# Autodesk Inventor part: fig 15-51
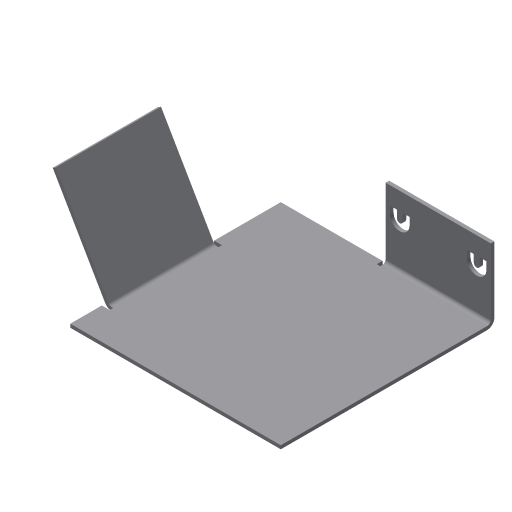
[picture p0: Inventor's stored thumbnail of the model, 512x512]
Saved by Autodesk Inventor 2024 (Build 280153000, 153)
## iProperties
Shininess: 77.0
Angle Display Precision: 2
Document Length Units: 11269
Document Angle Units: 11279
Document Time Units: 11290
Document Mass Units: 11283
Document Length Units Precision: 3
Document Angle Units Precision: 2
Created: 2002-04
Part Number: fig 15-51
Document SubType Name: Sheet Metal
Density: 1 g/cm^3
Sheet Metal Rule: Default
Material: Generic
Appearance: Default
Density: 0.0
Volumn: 0.0
Area: 0.0
PropertySet Name: Model Information
Control State: 0
Master: False
Checked Out: False
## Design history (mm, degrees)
node "Face1"
  sketch "Sketch1"
    geometry: L1 (12.647, 25.882)-(12.647, -14.118); L2 (12.647, -14.118)-(-17.353, -14.118); L3 (-17.353, -14.118)-(-17.353, 15.882); L4 (-17.353, 15.882)-(-2.353, 15.882); L5 (-2.353, 15.882)-(-2.353, 25.882); L6 (-2.353, 25.882)-(12.647, 25.882); 1 further point
    constraints: 12 end point, 4 parallel, 1 perpendicular
    dimensions: "d5" = 30 distance of L2.end L3.end; "d6" = 10 distance of L4.end L5.end; "d7" = 15 distance of L3.end L4.end; "d25" = 15 distance of L5.end L1.start
sketch "Sketch3"
  geometry: L1 (10, -15)-(10, 0)
  constraints: 2 end point
feature "Fold3" sketch "Sketch3" dims "d26" = 0.5 (= BendRadius), "d27" = 90 deg, "d28" = 0.5 (= BendRadius), "d96" = 0.5 (= BendReliefWidth), "d97" = 0.25 (= BendReliefDepth), "d98" = 1 (= MinimumRemnant), "d107" = 0.5 (= Thickness), "SeamGap" = 0.01
node "Flange2"
sketch "Sketch6"
  geometry: L1 (-6.914, 3.413)-(-5.843, 3.413); L2 (-5.843, 0.624)-(-6.914, 0.624); L3 (-6.914, 2.432)-(-5.843, 2.432); L4 (-5.843, 1.605)-(-6.914, 1.605); L5 (-6.914, 0.624)-(-6.914, 1.605); L6 (-6.914, 2.432)-(-6.914, 3.413); L7 (-6.914, 12.568)-(-6.914, 11.587); L8 (-6.914, 14.376)-(-6.914, 13.395); L9 (-6.914, 11.587)-(-5.843, 11.587); L10 (-5.843, 14.376)-(-6.914, 14.376); L11 (-6.914, 12.568)-(-5.843, 12.568); L12 (-5.843, 13.395)-(-6.914, 13.395); A1 r 1.394 centre (-5.843, 2.018) between (-5.843, 0.624) and (-5.843, 3.413); A2 r 0.413 centre (-5.843, 2.018) between (-5.843, 1.605) and (-5.843, 2.432); A3 r 1.394 centre (-5.843, 12.982) between (-5.843, 11.587) and (-5.843, 14.376); A4 r 0.413 centre (-5.843, 12.982) between (-5.843, 12.568) and (-5.843, 13.395)
  constraints: 24 end point, 8 point on circle, 4 centre point, 3 equal length, 1 perpendicular
cut "Cut1" sketch "Sketch6" dims "d49" = 0.5 (= Thickness), "d50" = 0
body "Solid1"
face "Plate1" dims "d107" = 0.5 (= Thickness)
sketch "Sketch5"
  geometry: L1 (20, 0)-(5, 0); L2 (5, 0)-(5, 15); L3 (5, 15)-(20, 15); L4 (20, 15)-(20, 0)
  constraints: 8 end point
face "Plate6" dims "d35" = 10, "d36" = 5, "d38" = 15, "d39" = 60 deg, "d40" = 0.5 (= BendRadius), "d107" = 0.5 (= Thickness), "MinimumRemnant" = 1 (= 2 x Thickness), "BendReliefWidth" = 0.5 (= Thickness)
bend "Bend5" dims "d38" = 15, "d39" = 60 deg, "d40" = 0.5 (= BendRadius), "d99" = 0.5 (= BendReliefWidth), "d100" = 0.25 (= BendReliefDepth), "d101" = 1 (= MinimumRemnant), "d107" = 0.5 (= Thickness), "SeamGap" = 0.01, "MinimumRemnant" = 1 (= 2 x Thickness), "BendReliefWidth" = 0.5 (= Thickness), "TransitionRadius" = 0.5 (= BendRadius)
other parameters: "Thickness" = 0.5, "BendRadius" = 0.5 (= Thickness), "BendReliefDepth" = 0.25 (= 0.5 x Thickness), "CornerReliefSize" = 2 (= 4 x Thickness), "d0" = 0.5 (= BendRadius), "d13" = 0.5 (= BendRadius), "d31" = 0.5 (= BendRadius), "d37" = 0.5 (= BendRadius), "JacobiRadiusSize" = 0.5 (= Thickness), "GapSize" = 0.5 (= Thickness)
